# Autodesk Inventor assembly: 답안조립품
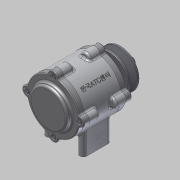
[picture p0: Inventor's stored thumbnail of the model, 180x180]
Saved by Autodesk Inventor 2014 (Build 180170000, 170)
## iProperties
Created: 2015-03
Part Number: 답안조립품
Document SubType Name: Assembly
Designer: MYHOME
Author: MYHOME
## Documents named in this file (11)
- C:\Documents and Settings\MYHOME\바탕 화면\450306V1018\답안조립품.iam
- C:\Documents and Settings\MYHOME\바탕 화면\450306V1018\본체.ipt
- C:\Documents and Settings\MYHOME\바탕 화면\450306V1018\커버2.ipt
- C:\Documents and Settings\MYHOME\바탕 화면\450306V1018\커버.ipt
- C:\Documents and Settings\MYHOME\바탕 화면\450306V1018\M 4 x 12.ipt
- C:\Documents and Settings\MYHOME\바탕 화면\450306V1018\축.ipt
- C:\Documents and Settings\MYHOME\바탕 화면\450306V1018\베어링 6204.ipt
- C:\Documents and Settings\MYHOME\바탕 화면\450306V1018\오일실.ipt
- C:\Documents and Settings\MYHOME\바탕 화면\450306V1018\키(4 x 4 x 12).ipt
- C:\Documents and Settings\MYHOME\바탕 화면\450306V1018\V벨트풀리.ipt
- C:\Documents and Settings\MYHOME\바탕 화면\450306V1018\너트 M12x1.25.ipt
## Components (14 placed, 6 different names)
1. KS B 2023 6204 - 20 x 47 x 14:1
2. KS B 2023 6204 - 20 x 47 x 14:2
3. KS B 2804 D D - 20 32 8:1
4. KS B 1311 (I) 4 x 4 x 12:1
5. 그루브 풀리1:1
6. KS B 1012 클래스 1 일반 - 미터 M12x1.25:1
7. KS B 1003 - 미터 M 4 x 12:2
8. KS B 1003 - 미터 M 4 x 12:3
9. KS B 1003 - 미터 M 4 x 12:4
10. KS B 1003 - 미터 M 4 x 12:5
11. KS B 1003 - 미터 M 4 x 12:1
12. KS B 1003 - 미터 M 4 x 12:6
13. KS B 1003 - 미터 M 4 x 12:7
14. KS B 1003 - 미터 M 4 x 12:8
